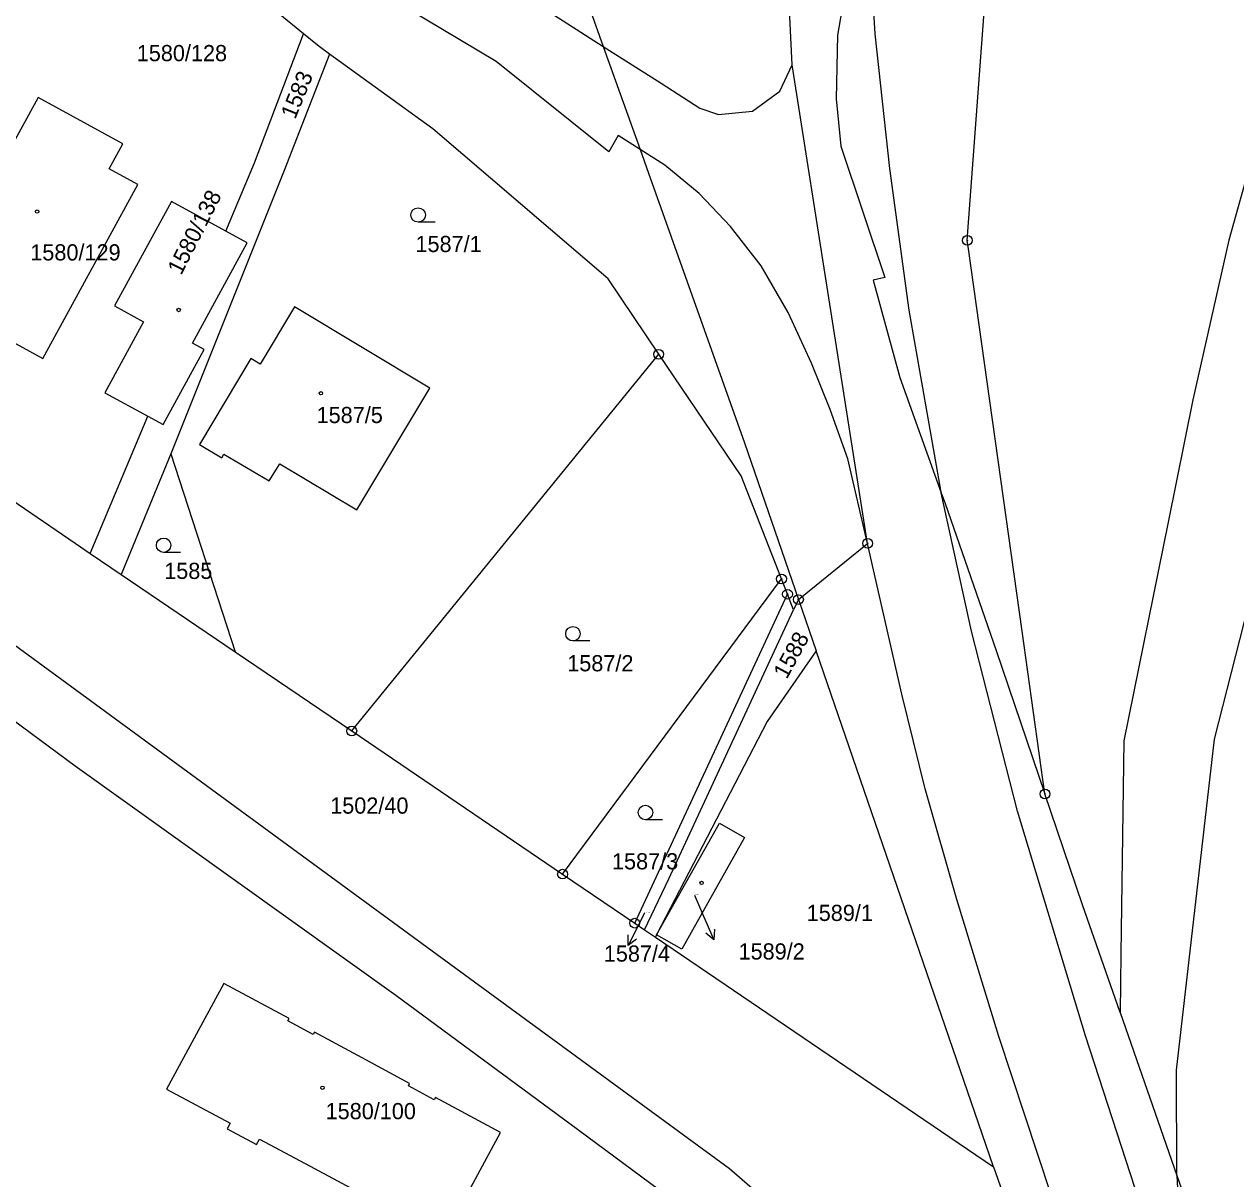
# Model space of a CAD drawing. Extents: x -737240 to -735272, y -1119606 to -1117878.
# Drawn here: x -735992.5 to -735865.3, y -1118331.1 to -1118209.9 of the extents above; entities that cross this region are included whole.
import ezdxf

# ---------------------------------------------------------------- set-up
doc = ezdxf.new("R2010")
doc.units = 0
for name, color, linetype in [('Level 1', 7, 'Continuous'), ('Level 16', 7, 'Continuous'), ('Level 18', 7, 'Continuous'), ('Level 19', 7, 'Continuous'), ('Level 25', 7, 'Continuous'), ('Level 4', 7, 'Continuous')]:
    doc.layers.add(name, color=color, linetype=linetype)

msp = doc.modelspace()

# ---------------------------------------------------------------- linework, layer by layer
at = {"layer": 'Level 1'}
for p, q in [((-735931.73, -1118212.19), (-735927.86, -1118223.01)), ((-735903.97, -1118264.38), (-735911.9, -1118214.13)), ((-735958.15, -1118284.08), (-735925.91, -1118244.52)), ((-735985.62, -1118265.43), (-735979.55, -1118251.02)), ((-735977.15, -1118254.97), (-735982.36, -1118267.64)), ((-735977.15, -1118254.97), (-735970.38, -1118275.78)), ((-735911.24, -1118270.28), (-735903.97, -1118264.38)), ((-735985.62, -1118265.43), (-735982.36, -1118267.64)), ((-735982.36, -1118267.64), (-735970.38, -1118275.78)), ((-735936.01, -1118299.12), (-735913.02, -1118268.12)), ((-735912.39, -1118269.72), (-735913.02, -1118268.12)), ((-735928.43, -1118304.27), (-735912.39, -1118269.72)), ((-735911.75, -1118271.35), (-735912.39, -1118269.72)), ((-735911.24, -1118270.28), (-735911.75, -1118271.35)), ((-735911.24, -1118270.28), (-735909.39, -1118275.67)), ((-735970.38, -1118275.78), (-735958.15, -1118284.08)), ((-735890.77, -1118329.85), (-735909.39, -1118275.67)), ((-735958.15, -1118284.08), (-735936.01, -1118299.12)), ((-735936.01, -1118299.12), (-735928.43, -1118304.27)), ((-735928.43, -1118304.27), (-735927.42, -1118304.96)), ((-735927.42, -1118304.96), (-735926.26, -1118305.75)), ((-735926.13, -1118305.49), (-735926.26, -1118305.75)), ((-735926.26, -1118305.75), (-735890.77, -1118329.85)), ((-735877.46, -1118313.64), (-735871.5, -1118330.76)), ((-735871.5, -1118330.76), (-735863.57, -1118353.56))]:
    msp.add_line(p, q, dxfattribs=at)
for points in [[(-735911.9, -1118214.13), (-735912.98, -1118191.78), (-735913.54, -1118172.55)], [(-736132.41, -1118173.31), (-735949.71, -1118307.16), (-735930.63, -1118321.15), (-735918.49, -1118330.04), (-735910.8, -1118336.7), (-735905.76, -1118341.88), (-735900.15, -1118348.58), (-735894.58, -1118356.95), (-735890.02, -1118365.43), (-735887.12, -1118371.18), (-735881.94, -1118383.37), (-735878.62, -1118392.03), (-735872.34, -1118409.36), (-735867.8, -1118422.01), (-735863.53, -1118434.8)], [(-735885.35, -1118290.7), (-735887.75, -1118273.61), (-735893.39, -1118233.44), (-735893.51, -1118232.56), (-735892.16, -1118214.22), (-735889.58, -1118179.35)], [(-735963.22, -1118210.87), (-735978.13, -1118198.64), (-735983.31, -1118192.34), (-735986.91, -1118187.96)], [(-735942.24, -1118188.79), (-735934.03, -1118205.77), (-735931.73, -1118212.19)], [(-735904.09, -1118196.7), (-735904.96, -1118198.45), (-735907.14, -1118211.02), (-735907.28, -1118217.69), (-735906.8, -1118222.67), (-735902.15, -1118236.46), (-735903.39, -1118236.73), (-735900.58, -1118246.95), (-735896.25, -1118259.08)], [(-735856.51, -1118198.68), (-735859.17, -1118203.26), (-735859.35, -1118203.58), (-735860.71, -1118205.91), (-735860.09, -1118211.18), (-735862.69, -1118220.54), (-735866.03, -1118232.55), (-735869.82, -1118249.31), (-735872.42, -1118262.14), (-735877.08, -1118285.12), (-735877.38, -1118307.48), (-735877.46, -1118313.64)], [(-735971.37, -1118231.59), (-735968.35, -1118224.41), (-735963.22, -1118210.87)], [(-735960.48, -1118213), (-735961.58, -1118212.21), (-735963.22, -1118210.87)], [(-735960.48, -1118213), (-735965.26, -1118225.23), (-735977.15, -1118254.97)], [(-735925.91, -1118244.52), (-735931.23, -1118236.61), (-735949.63, -1118220.84), (-735960.48, -1118213)], [(-735980.61, -1118226.7), (-735983.62, -1118225.05), (-735982.19, -1118222.42), (-735991.1, -1118217.54), (-736002.53, -1118238.42), (-735990.61, -1118244.96), (-735980.61, -1118226.7)], [(-735927.86, -1118223.01), (-735926.97, -1118225.49), (-735916.92, -1118253.82), (-735911.24, -1118270.28)], [(-735971.37, -1118231.59), (-735977.08, -1118228.48), (-735983.08, -1118239.44), (-735980.03, -1118241.12), (-735984.08, -1118248.56), (-735979.55, -1118251.02)], [(-735979.55, -1118251.02), (-735977.96, -1118251.89), (-735973.64, -1118244.02), (-735974.87, -1118243.35), (-735969.13, -1118232.81), (-735971.37, -1118231.59)], [(-735967.78, -1118245.57), (-735968.76, -1118244.98), (-735974.14, -1118254), (-735971.8, -1118255.4), (-735971.57, -1118255.02), (-735966.81, -1118257.83), (-735965.71, -1118256.03), (-735957.63, -1118260.87), (-735949.95, -1118248.07), (-735964.18, -1118239.55), (-735967.78, -1118245.57)], [(-735913.02, -1118268.12), (-735917.27, -1118257.28), (-735925.91, -1118244.52)], [(-735882.16, -1118401.98), (-735884.31, -1118394.32), (-735887.57, -1118385.55), (-735892.14, -1118374.64), (-735895.59, -1118367.84), (-735899.94, -1118359.98), (-735904.37, -1118353.42), (-735910.3, -1118346.1), (-735915.18, -1118341), (-735921.08, -1118335.86), (-735934.46, -1118325.93), (-735953.53, -1118311.86), (-735987.19, -1118287.78), (-736042.03, -1118247.22)], [(-736011.5, -1118247.82), (-736007.28, -1118250.69), (-735993.86, -1118259.82), (-735987.2, -1118264.36), (-735985.62, -1118265.43)], [(-735896.25, -1118259.08), (-735895.84, -1118260.21), (-735890.47, -1118275.65), (-735885.35, -1118290.7)], [(-735927.42, -1118304.96), (-735924.85, -1118299.6), (-735911.75, -1118271.35)], [(-735909.39, -1118275.67), (-735914.51, -1118283.09), (-735926.13, -1118305.49)], [(-735877.46, -1118313.64), (-735881.39, -1118302.35), (-735885.35, -1118290.7)], [(-735926.13, -1118305.49), (-735919.52, -1118293.78), (-735916.91, -1118295.27), (-735923.5, -1118306.99), (-735926.13, -1118305.49)], [(-735963.03, -1118329.52), (-735958.22, -1118332.09), (-735958.53, -1118332.66), (-735955.44, -1118334.31), (-735955.14, -1118333.74), (-735948.48, -1118337.3), (-735942.52, -1118326.26), (-735949.37, -1118322.57), (-735949.51, -1118322.82), (-735952.2, -1118321.36), (-735952.07, -1118321.11), (-735957.07, -1118318.42), (-735962.08, -1118315.73), (-735962.21, -1118315.97), (-735964.86, -1118314.54), (-735964.73, -1118314.3), (-735971.6, -1118310.59), (-735977.6, -1118321.72), (-735970.93, -1118325.29), (-735971.25, -1118325.88), (-735968.16, -1118327.53), (-735967.84, -1118326.94), (-735963.03, -1118329.52)], [(-735890.77, -1118329.85), (-735886.52, -1118341.93), (-735878.2, -1118368.98), (-735871.31, -1118389.76), (-735858.97, -1118425.18), (-735845.83, -1118463.37)]]:
    msp.add_lwpolyline(points, dxfattribs=at)
at = {"layer": 'Level 16'}
for points in [[(-735922.17, -1118301.32), (-735921.31, -1118303.28), (-735920.11, -1118306.03)], [(-735927.39, -1118303.18), (-735927.77, -1118303.93), (-735929.127, -1118306.605)], [(-735928.229, -1118305.94), (-735929.127, -1118306.605), (-735929.121, -1118305.487)], [(-735920.052, -1118304.913), (-735920.11, -1118306.03), (-735920.968, -1118305.313)]]:
    msp.add_lwpolyline(points, dxfattribs=at)
at = {"layer": 'Level 25'}
for p, q in [((-735949.398, -1118230.65), (-735951.18, -1118230.65)), ((-735976.128, -1118265.33), (-735977.91, -1118265.33)), ((-735933.138, -1118274.63), (-735934.92, -1118274.63)), ((-735925.528, -1118293.4), (-735927.31, -1118293.4))]:
    msp.add_line(p, q, dxfattribs=at)
for centre, major_axis, ratio in [((-735951.18, -1118229.894), (0.764, 0), 0.9894236), ((-735991.19, -1118229.53), (0.18, 0), 0.9848078), ((-735893.51, -1118232.56), (0.516, 0), 0.9848078), ((-735893.51, -1118232.56), (0.0375, 0), 0.9848078), ((-735976.33, -1118239.87), (0.18, 0), 0.9848078), ((-735925.91, -1118244.52), (0.516, 0), 0.9848078), ((-735925.91, -1118244.52), (0.0375, 0), 0.9848078), ((-735961.39, -1118248.62), (0.18, 0), 0.9848078), ((-735977.91, -1118264.574), (0.764, 0), 0.9894236), ((-735903.97, -1118264.38), (0.516, 0), 0.9848078), ((-735903.97, -1118264.38), (0.0375, 0), 0.9848078), ((-735913.02, -1118268.12), (0.516, 0), 0.9848078), ((-735913.02, -1118268.12), (0.0375, 0), 0.9848078), ((-735912.39, -1118269.72), (0.516, 0), 0.9848078), ((-735912.39, -1118269.72), (0.0375, 0), 0.9848078), ((-735911.24, -1118270.28), (0.516, 0), 0.9848078), ((-735911.24, -1118270.28), (0.0375, 0), 0.9848078), ((-735934.92, -1118273.874), (0.764, 0), 0.9894236), ((-735958.15, -1118284.08), (0.516, 0), 0.9848078), ((-735958.15, -1118284.08), (0.0375, 0), 0.9848078), ((-735885.35, -1118290.7), (0.516, 0), 0.9848078), ((-735885.35, -1118290.7), (0.0375, 0), 0.9848078), ((-735927.31, -1118292.644), (0.764, 0), 0.9894236), ((-735936.01, -1118299.12), (0.516, 0), 0.9848078), ((-735936.01, -1118299.12), (0.0375, 0), 0.9848078), ((-735921.41, -1118300.04), (0.18, 0), 0.9848078), ((-735928.43, -1118304.27), (0.516, 0), 0.9848078), ((-735928.43, -1118304.27), (0.0375, 0), 0.9848078), ((-735961.22, -1118321.56), (0.18, 0), 0.9848078)]:
    msp.add_ellipse(centre, major_axis=major_axis, ratio=ratio, dxfattribs=at)
at = {"layer": 'Level 4'}
for points in [[(-735871.5, -1118330.76), (-735871.55, -1118319.72), (-735867.56, -1118284.96), (-735861.3, -1118260.51), (-735853.71, -1118240.23), (-735843.06, -1118218.78), (-735829.23, -1118197.5), (-735817.43, -1118182.83), (-735805.32, -1118169.95), (-735789.91, -1118156.35), (-735773.8, -1118145.05), (-735758.53, -1118135.93), (-735749.12, -1118131.38)], [(-735942.24, -1118188.79), (-735944.42, -1118189.24), (-735950.86, -1118189.35), (-735956.74, -1118188.63), (-735961.91, -1118187.35), (-735967.01, -1118185.19), (-735972.94, -1118181.47), (-735978.89, -1118176.55), (-735973.85, -1118182.47), (-735967.24, -1118188.69), (-735956.3, -1118196.99), (-735937.82, -1118208.32), (-735931.73, -1118212.19)], [(-735904.09, -1118196.7), (-735903.21, -1118210.88), (-735901.68, -1118225.02), (-735899.66, -1118239.9), (-735896.31, -1118258.78), (-735896.25, -1118259.08)], [(-735927.86, -1118223.01), (-735930.16, -1118221.54), (-735931.16, -1118223.27), (-735942.97, -1118213.77), (-735956.09, -1118205.92)], [(-735931.73, -1118212.19), (-735925.65, -1118216.06), (-735921.58, -1118218.67), (-735919.65, -1118219.34), (-735916.07, -1118218.99), (-735913.19, -1118216.89), (-735911.9, -1118214.13)], [(-735903.97, -1118264.38), (-735906.06, -1118255.52), (-735907.89, -1118250.32), (-735909.88, -1118245.45), (-735912.33, -1118240.15), (-735915.17, -1118235.24), (-735918.37, -1118231.11), (-735921.66, -1118227.64), (-735925.27, -1118224.66), (-735927.86, -1118223.01)], [(-735871.5, -1118330.76), (-735870.75, -1118344.99), (-735871.64, -1118345.15), (-735881.09, -1118316.09), (-735888.24, -1118292.52), (-735893.07, -1118273.61), (-735896.25, -1118259.08)], [(-735839.74, -1118462.4), (-735850.81, -1118429.97), (-735859.94, -1118404.04), (-735870.64, -1118374.06), (-735884.74, -1118332.69), (-735890.21, -1118316.17), (-735894.62, -1118301.8), (-735897.92, -1118290.15), (-735900.38, -1118280.22), (-735903.97, -1118264.38)]]:
    msp.add_lwpolyline(points, dxfattribs=at)

# ---------------------------------------------------------------- texts
at = {"layer": 'Level 16'}
for s, p in [('1587/4', (-735931.68, -1118308.31)), ('1589/2', (-735917.53, -1118308.09))]:
    msp.add_text(s, height=1.7, dxfattribs=at).set_placement(p)
at = {"layer": 'Level 18'}
for s, height, p in [('1580/128', 1.7, (-735980.73, -1118213.74)), ('1587/1', 1.7, (-735951.46, -1118233.79)), ('1585', 1.7, (-735977.85, -1118268.12)), ('1587/2', 1.7, (-735935.52, -1118277.82)), ('1502/40', 1.7, (-735960.415, -1118292.77)), ('1587/3', 1.7, (-735930.82, -1118298.62)), ('1589/1', 1.7, (-735910.37, -1118304.04)), ('1587/4', 0.1, (-735927.24, -1118303.18))]:
    msp.add_text(s, height=height, dxfattribs=at).set_placement(p)
for s, rotation, p in [('1583', 67.75101, (-735964.096, -1118219.917)), ('1588', 61.49862, (-735912.469, -1118278.726))]:
    msp.add_text(s, height=1.7, rotation=rotation, dxfattribs=at).set_placement(p)
at = {"layer": 'Level 19'}
msp.add_text('1580/138', height=1.7, rotation=63, dxfattribs=at).set_placement((-735976.07, -1118236.29))
for s, height, p in [('1580/129', 1.7, (-735991.91, -1118234.67)), ('1587/5', 1.7, (-735961.84, -1118251.75)), ('1589/2', 0.1, (-735922.17, -1118301.32)), ('1580/100', 1.7, (-735960.895, -1118324.86))]:
    msp.add_text(s, height=height, dxfattribs=at).set_placement(p)

doc.saveas('drawing.dxf')
